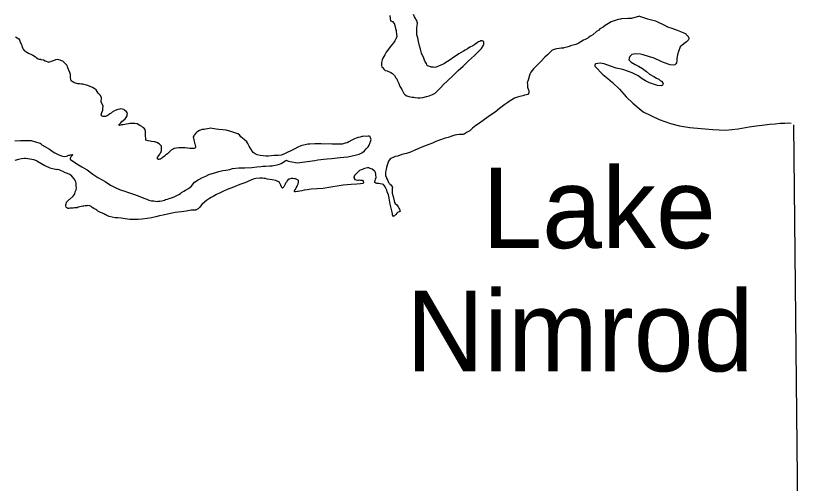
# Model space of a CAD drawing. Extents: x -83719 to 153526, y -11835 to 11446.
# Drawn here: x -2511.6 to -2340.9, y -912 to -809.8 of the extents above; entities that cross this region are included whole.
import ezdxf

# ---------------------------------------------------------------- set-up
doc = ezdxf.new("R2010")
doc.units = 0
doc.layers.add('Level 2', color=7, linetype='Continuous')
doc.layers.add('Level 9', color=7, linetype='Continuous')

msp = doc.modelspace()

# ---------------------------------------------------------------- linework, layer by layer
at = {"layer": 'Level 2'}
msp.add_lwpolyline([(-2341.72, -833.65), (-2340.87, -917.74), (-2428.7, -919.72), (-2427.14, -1008.01)], dxfattribs=at)
at = {"layer": 'Level 9'}
for points in [[(-2429.85, -809.82), (-2429.76, -810.45), (-2429.72, -810.95), (-2429.68, -810.95), (-2429.51, -811.04), (-2429.28, -811.14), (-2429.24, -811.14), (-2428.97, -811.46), (-2428.86, -811.66), (-2428.78, -812.09), (-2428.71, -812.26), (-2428.64, -812.62), (-2428.49, -813.09), (-2428.45, -813.29), (-2428.37, -813.88), (-2428.35, -814.42), (-2428.48, -814.75), (-2428.79, -815.36), (-2429.05, -815.74), (-2429.44, -816.22), (-2429.79, -816.63), (-2430.18, -817.17), (-2430.63, -817.82)], [(-2415.97, -818.94), (-2416.08, -819.02), (-2416.47, -819.36), (-2417.26, -819.85), (-2417.65, -820.1), (-2417.95, -820.27), (-2418.48, -820.59), (-2419.1, -820.77), (-2419.73, -821.09), (-2420.06, -821.13), (-2420.29, -821.1), (-2420.6, -821.05), (-2420.86, -821.05), (-2420.93, -821.02), (-2421.43, -820.9), (-2421.67, -820.78), (-2421.78, -820.58), (-2421.88, -820.31), (-2422.13, -819.92), (-2422.27, -819.59), (-2422.45, -819.13), (-2422.92, -818.01), (-2423.17, -817.14), (-2423.36, -816.42), (-2423.59, -815.49), (-2423.74, -814.69), (-2423.93, -814.03), (-2423.98, -813.4), (-2423.99, -812.93), (-2423.96, -812.69), (-2423.94, -812.43), (-2423.88, -812.12), (-2423.85, -811.89), (-2423.83, -811.59), (-2423.83, -811.45), (-2423.87, -811.26), (-2423.98, -810.92), (-2424.05, -810.79), (-2424.16, -810.6), (-2424.26, -810.43), (-2424.5, -810.07), (-2424.72, -809.61)], [(-2375.36, -809.93), (-2377.1, -810.43), (-2377.47, -810.44), (-2377.87, -810.45), (-2379.3, -810.56), (-2379.5, -810.59), (-2380.03, -810.68), (-2380.43, -810.79), (-2381.12, -811.07), (-2381.52, -811.22), (-2382.11, -811.57), (-2382.47, -811.78), (-2382.86, -811.99), (-2383.25, -812.33), (-2383.71, -812.55), (-2383.98, -812.72), (-2384.2, -812.99), (-2384.73, -813.28), (-2385.51, -814.03), (-2386, -814.31), (-2386.43, -814.56), (-2386.59, -814.73), (-2387.18, -815.05), (-2387.54, -815.19), (-2388.17, -815.54), (-2388.72, -815.89), (-2389.25, -816.11), (-2389.85, -816.29), (-2390.41, -816.44), (-2390.71, -816.58), (-2391.2, -816.69), (-2391.83, -816.88), (-2391.9, -816.91), (-2392.23, -816.92), (-2392.43, -816.96), (-2392.89, -817.01), (-2393.39, -817.09), (-2393.76, -817.13), (-2394.38, -817.38), (-2394.84, -817.8), (-2395.39, -818.41), (-2396.04, -818.9), (-2396.88, -819.82), (-2397.21, -820.2), (-2397.86, -820.78), (-2398.47, -821.47), (-2399.09, -822.19), (-2399.31, -822.59), (-2399.46, -823.1), (-2399.64, -823.94), (-2399.8, -824.28), (-2399.86, -824.54), (-2399.82, -824.78), (-2399.81, -825.14), (-2399.76, -825.44), (-2399.69, -825.67), (-2399.65, -825.87), (-2399.58, -826.04), (-2399.51, -826.17), (-2399.51, -826.2), (-2399.5, -826.4), (-2399.5, -826.57), (-2399.53, -826.74), (-2399.59, -826.87), (-2399.69, -827.04), (-2400.02, -827.15), (-2400.45, -827.23), (-2400.58, -827.27), (-2400.84, -827.38), (-2401.47, -827.49), (-2401.94, -827.64), (-2402.63, -827.89), (-2403.22, -828.21), (-2403.58, -828.42), (-2403.81, -828.59), (-2404.11, -828.8), (-2404.76, -829.22), (-2405.9, -830.12), (-2406.88, -830.88), (-2407.9, -831.54), (-2409.99, -833.1), (-2410.51, -833.45), (-2411.04, -833.83), (-2411.79, -834.39), (-2412.4, -834.97), (-2412.54, -835.04), (-2412.96, -835.26), (-2413.65, -835.71), (-2413.85, -835.78), (-2414.38, -835.8), (-2414.62, -835.77), (-2415.25, -835.85), (-2415.68, -835.97), (-2416.31, -836.18), (-2417.13, -836.41), (-2417.8, -836.59), (-2418.98, -837.06), (-2419.78, -837.35), (-2420.57, -837.67), (-2421.36, -837.96), (-2421.92, -838.21)], [(-2375.36, -809.93), (-2373.56, -810.51), (-2371.85, -810.96), (-2369.87, -811.94), (-2369.24, -812.27), (-2368.3, -812.56), (-2367.1, -812.98), (-2366.39, -813.28), (-2365.66, -813.6), (-2365.25, -813.83), (-2365.12, -813.96), (-2364.65, -814.46), (-2364.54, -814.79), (-2364.67, -815.13), (-2365.04, -815.56), (-2365.67, -816), (-2366.43, -816.65), (-2366.82, -817.68), (-2367.07, -818.42), (-2367.17, -819.22), (-2367.2, -819.69), (-2367.26, -820.13), (-2367.39, -820.36), (-2367.62, -820.6), (-2367.95, -820.67), (-2368.65, -820.61), (-2370.09, -820.09), (-2370.76, -819.76), (-2372.1, -819.14), (-2373.37, -818.75), (-2374.51, -818.4), (-2375.14, -818.27), (-2376.15, -818.18), (-2377.04, -818.35), (-2377.47, -818.79), (-2377.6, -819.13), (-2377.63, -819.49), (-2377.16, -820.02), (-2376.29, -820.48), (-2375.55, -820.84), (-2374.68, -821.37), (-2373.84, -822.06), (-2373.13, -822.62), (-2372.19, -823.14), (-2371.62, -823.47), (-2371.09, -823.73), (-2370.82, -824), (-2370.55, -824.16), (-2370.21, -824.49), (-2370.18, -824.73), (-2370.31, -825.03), (-2370.61, -825.13), (-2371.44, -825.07), (-2373.15, -824.52), (-2374.05, -824.1), (-2374.76, -823.6), (-2375.66, -823.01), (-2376.97, -822.32), (-2378.98, -821.58), (-2380.45, -821.29), (-2381.69, -820.87), (-2383.03, -820.38), (-2383.96, -820.22), (-2384.46, -820.26), (-2384.86, -820.37), (-2385.03, -820.44), (-2385.09, -820.67), (-2385.09, -820.9), (-2383.37, -822.72), (-2382.26, -823.58), (-2381.22, -824.44), (-2379.74, -825.89), (-2378.22, -827.54), (-2376.77, -828.96), (-2374.52, -830.84), (-2371.03, -832.54), (-2368.59, -833.42), (-2366.58, -833.93), (-2364.38, -834.25), (-2361.88, -834.46), (-2359.34, -834.73), (-2356.54, -834.84), (-2353.81, -834.54), (-2351.38, -834.15), (-2349.88, -833.87), (-2348.55, -833.72), (-2346.92, -833.54), (-2345.72, -833.46), (-2344.65, -833.35), (-2343.62, -833.31), (-2342.75, -833.23), (-2342.19, -833.31)], [(-2511.57, -814.43), (-2511.23, -814.66), (-2510.86, -814.88), (-2510.72, -815.11), (-2510.54, -815.64), (-2510.29, -816.17), (-2510.22, -816.46), (-2510.14, -816.66), (-2510.07, -816.86), (-2509.93, -817.16), (-2509.72, -817.45), (-2509.52, -817.55), (-2509.11, -817.8), (-2508.77, -818.02), (-2508.13, -818.31), (-2507.79, -818.46), (-2507.22, -818.85), (-2506.98, -819.08), (-2506.61, -819.23), (-2506.41, -819.33), (-2506.3, -819.36), (-2506.07, -819.35), (-2506.04, -819.38)], [(-2430.63, -817.82), (-2430.98, -818.36), (-2431.36, -819.11), (-2431.51, -819.48), (-2431.66, -820.08), (-2431.65, -820.65), (-2431.57, -821.05), (-2431.43, -821.15), (-2431.09, -821.6), (-2430.85, -821.83), (-2430.41, -821.92), (-2429.67, -822.23), (-2429.3, -822.46), (-2428.85, -822.94), (-2428.54, -823.4), (-2428.33, -823.63), (-2428.15, -824.06), (-2428.04, -824.39), (-2427.9, -824.65), (-2427.68, -825.31), (-2427.47, -825.61), (-2427.2, -825.97), (-2426.81, -826.83), (-2426.67, -826.99), (-2426.5, -827.12), (-2426.16, -827.31), (-2425.69, -827.46), (-2424.95, -827.64), (-2424.61, -827.67), (-2424.35, -827.73), (-2423.74, -827.78), (-2423.21, -827.76), (-2422.68, -827.68), (-2421.85, -827.49), (-2421.29, -827.34), (-2420.56, -827.09), (-2419.97, -826.74), (-2419.22, -826.02), (-2418.77, -825.57), (-2418.06, -824.81), (-2417.34, -824.16), (-2416.04, -822.92), (-2414.94, -821.79), (-2413.83, -820.86), (-2412.7, -819.73), (-2411.36, -818.52), (-2410.62, -817.8), (-2409.84, -817.01), (-2409.45, -816.46), (-2409.33, -816.06), (-2409.34, -815.76), (-2409.34, -815.53), (-2409.51, -815.4), (-2409.72, -815.3), (-2409.95, -815.34), (-2410.18, -815.45), (-2410.51, -815.56), (-2410.71, -815.7), (-2411.29, -816.15), (-2411.75, -816.43), (-2412.38, -816.75), (-2412.87, -817.06), (-2413.4, -817.37), (-2413.79, -817.62)], [(-2413.79, -817.62), (-2414.77, -818.19), (-2415.97, -818.94)], [(-2506.04, -819.38), (-2505.51, -819.46), (-2505.1, -819.68), (-2504.3, -819.96)], [(-2490, -830.65), (-2490.46, -830.93), (-2490.69, -831.1), (-2491.01, -831.31), (-2491.37, -831.55), (-2491.6, -831.69), (-2491.77, -831.76), (-2491.97, -831.87), (-2492.27, -831.88), (-2492.5, -831.85), (-2492.67, -831.79), (-2492.74, -831.72), (-2492.84, -831.63), (-2492.88, -831.56), (-2492.85, -831.46), (-2492.72, -830.99), (-2492.54, -830.48), (-2492.51, -830.15), (-2492.43, -829.54), (-2492.85, -828.76), (-2492.82, -827.72), (-2493.1, -827.23), (-2493.54, -826.74), (-2493.96, -826.02), (-2494.44, -825.73), (-2494.75, -825.5), (-2495.25, -825.32), (-2495.82, -825.1), (-2496.06, -825), (-2496.56, -824.85), (-2496.9, -824.83), (-2497.23, -824.77), (-2497.64, -824.71), (-2498, -824.69), (-2498.71, -824.51), (-2498.88, -824.42), (-2499.22, -824.22), (-2499.42, -824.1), (-2499.49, -823.8), (-2499.57, -823.33), (-2499.59, -822.7), (-2499.74, -822.27), (-2500.02, -821.58), (-2500.21, -820.98), (-2500.28, -820.72), (-2500.66, -820.33), (-2501.27, -819.77), (-2501.51, -819.68), (-2501.81, -819.59), (-2502.15, -819.47), (-2502.38, -819.44), (-2502.35, -819.44), (-2502.85, -819.48), (-2502.98, -819.52), (-2503.38, -819.7), (-2503.57, -819.81), (-2503.84, -819.88), (-2503.91, -819.91), (-2504.17, -819.96), (-2504.3, -819.96)], [(-2472.68, -836.84), (-2472.65, -836.98), (-2472.57, -837.24), (-2472.49, -837.67), (-2472.42, -837.84), (-2472.35, -838.14), (-2472.31, -838.3), (-2472.3, -838.63), (-2472.43, -838.77), (-2472.59, -838.88), (-2472.69, -838.88), (-2473.26, -838.83), (-2473.53, -838.84), (-2474.03, -838.78), (-2474.57, -838.73), (-2475.07, -838.71), (-2475.93, -838.7), (-2476.4, -838.75), (-2476.93, -838.86), (-2477.16, -839), (-2477.59, -839.21), (-2478.11, -839.73), (-2478.4, -840.01), (-2478.73, -840.21), (-2479.09, -840.49), (-2479.31, -840.73), (-2479.54, -840.9), (-2479.61, -840.97), (-2479.77, -841.04), (-2479.87, -841.15), (-2480.07, -841.19), (-2480.3, -841.26), (-2480.37, -841.26), (-2480.4, -841.23), (-2480.47, -841.2), (-2480.54, -841.17), (-2480.57, -841.13), (-2480.61, -841), (-2480.55, -840.77), (-2480.45, -840.56), (-2480.1, -840.05), (-2479.97, -839.88), (-2479.88, -839.71), (-2479.72, -839.27), (-2479.7, -838.91), (-2479.68, -838.47), (-2479.71, -838.37), (-2479.88, -838.21), (-2480.13, -837.92), (-2480.36, -837.76), (-2480.74, -837.57), (-2481.14, -837.41), (-2481.34, -837.38), (-2481.91, -837.3), (-2482.18, -837.24), (-2482.61, -837.18), (-2483.12, -837.06), (-2483.12, -837.03), (-2483.12, -836.93), (-2483.12, -836.83), (-2483.16, -836.57), (-2483.18, -836.16), (-2483.22, -835.87), (-2483.23, -835.4), (-2483.23, -835.23), (-2483.28, -834.73), (-2483.56, -834.34), (-2483.83, -834.18), (-2484.03, -834.05), (-2484.41, -833.83), (-2485.05, -833.48), (-2485.52, -833.39), (-2485.92, -833.4), (-2486.59, -833.39), (-2486.95, -833.47), (-2487.45, -833.55), (-2487.75, -833.59), (-2488.18, -833.67), (-2488.41, -833.67), (-2488.58, -833.78), (-2488.88, -833.79), (-2488.98, -833.79), (-2488.92, -833.55), (-2488.89, -833.52), (-2488.59, -833.24), (-2488.37, -832.97), (-2488.07, -832.73), (-2487.62, -832.35), (-2487.39, -832.08), (-2487.23, -831.74), (-2487.18, -831.44), (-2487.15, -831.1), (-2487.36, -830.84), (-2487.77, -830.45), (-2487.94, -830.32), (-2488.28, -830.23), (-2488.61, -830.21), (-2488.84, -830.25), (-2489.27, -830.33), (-2489.83, -830.57), (-2490, -830.65)], [(-2450.1, -841.96), (-2446.21, -841.48), (-2445.58, -841.33), (-2444.95, -841.25), (-2444.28, -841.2), (-2443.52, -841.14), (-2442.59, -841.05), (-2440.69, -840.83), (-2439.89, -840.77), (-2439.03, -840.68), (-2438.07, -840.46), (-2437.14, -840.26), (-2436.58, -840.08), (-2435.82, -839.69), (-2435.4, -839.35), (-2435.01, -838.94), (-2434.62, -838.49), (-2434.39, -838.15), (-2434.18, -837.55), (-2434.15, -837.44), (-2434.08, -837.34), (-2433.99, -837.11), (-2433.9, -836.87), (-2434, -836.67), (-2434.04, -836.57), (-2434.18, -836.21), (-2434.38, -836.18), (-2434.55, -836.19), (-2435.05, -836.2), (-2435.28, -836.17), (-2435.75, -836.22), (-2435.98, -836.26), (-2436.31, -836.4), (-2436.74, -836.48), (-2437.24, -836.6), (-2437.6, -836.74), (-2438.16, -837.05), (-2438.78, -837.41), (-2439.15, -837.58), (-2439.61, -837.66), (-2440.27, -837.88), (-2440.54, -837.92), (-2440.84, -837.93), (-2441.64, -837.92), (-2442.41, -837.87), (-2443.07, -837.86), (-2444.07, -837.89), (-2444.88, -837.84), (-2445.58, -837.83), (-2446.24, -837.85), (-2447.31, -837.88), (-2447.77, -837.92), (-2449.3, -838.23), (-2449.96, -838.58), (-2450.61, -838.94), (-2451.47, -839.33), (-2452.29, -839.72), (-2453.02, -840.07), (-2453.61, -840.29), (-2454.21, -840.37), (-2454.71, -840.35), (-2455.14, -840.4), (-2455.77, -840.48), (-2456.37, -840.53), (-2456.91, -840.51), (-2457.51, -840.46), (-2458.18, -840.35), (-2458.82, -840.23), (-2459.29, -840.01), (-2459.66, -839.75), (-2459.84, -839.49), (-2460.19, -838.93), (-2460.57, -838.31), (-2460.89, -837.72), (-2461.1, -837.42), (-2461.64, -836.9), (-2462.36, -836.32), (-2462.71, -835.87), (-2463.05, -835.67), (-2463.89, -835.33), (-2464.76, -835.05), (-2465.6, -834.81), (-2466.34, -834.76), (-2467.17, -834.72), (-2467.74, -834.6), (-2468.62, -834.46), (-2468.95, -834.44), (-2469.68, -834.56), (-2470.08, -834.6), (-2470.41, -834.68), (-2470.81, -834.72), (-2471.4, -834.94), (-2471.77, -835.11), (-2471.96, -835.29), (-2472.19, -835.53), (-2472.58, -835.9), (-2472.58, -835.94), (-2472.67, -836.07), (-2472.77, -836.31), (-2472.72, -836.68), (-2472.68, -836.84)], [(-2505.81, -838.03), (-2505.84, -838.04), (-2506.01, -837.91), (-2506.18, -837.78), (-2507.13, -837.44), (-2508.13, -837.17), (-2509.43, -837.2), (-2510.49, -837.2), (-2511.76, -837.27)], [(-2505.84, -838.04), (-2504.17, -838.98), (-2503.6, -839.4), (-2503.33, -839.56), (-2502.98, -839.82), (-2502.54, -840.04), (-2502.14, -840.23), (-2501.57, -840.48), (-2501.23, -840.54), (-2500.93, -840.63), (-2500.43, -840.55), (-2500.27, -840.44), (-2499.94, -840.33), (-2499.74, -840.3), (-2499.57, -840.22), (-2499.27, -840.22), (-2499.14, -840.18), (-2499.1, -840.24), (-2499.14, -840.28), (-2499.17, -840.31), (-2499.36, -840.49), (-2499.36, -840.52), (-2499.43, -840.59), (-2499.52, -840.76), (-2499.55, -840.82), (-2499.65, -841.03), (-2499.68, -841.2), (-2499.58, -841.26), (-2498.22, -842.19), (-2497.84, -842.41), (-2497.1, -842.86), (-2495.95, -843.5), (-2494.68, -844.46), (-2493.63, -845.2), (-2492.04, -846.09), (-2490.82, -846.83), (-2490, -847.3), (-2488.89, -847.77), (-2488.45, -847.96), (-2487.74, -848.18), (-2487.37, -848.3), (-2485.83, -848.79), (-2484.81, -849.2), (-2483.94, -849.54), (-2483.33, -849.76), (-2482.93, -849.91), (-2482.49, -850.1), (-2481.92, -850.25), (-2481.38, -850.3), (-2480.64, -850.42), (-2480.45, -850.34), (-2480.11, -850.37), (-2479.61, -850.29), (-2479.02, -850.1), (-2478.82, -850), (-2478.39, -849.89), (-2478.06, -849.74), (-2477.33, -849.52), (-2476.77, -849.31), (-2476.51, -849.17), (-2475.92, -848.92), (-2475.59, -848.64), (-2475.36, -848.47), (-2474.84, -848.19), (-2474.44, -847.97), (-2473.82, -847.56), (-2473.46, -847.28), (-2473.26, -847.17), (-2472.52, -846.19), (-2471.71, -845.66), (-2470.79, -845.17), (-2470.06, -844.88), (-2469.4, -844.53), (-2467.61, -844.05), (-2467.22, -843.9), (-2466.32, -843.68), (-2465.69, -843.59), (-2464.8, -843.4), (-2464.2, -843.22), (-2462.84, -843.08), (-2461.51, -843.04), (-2460.01, -842.97), (-2458.88, -842.84), (-2458.05, -842.75), (-2457.58, -842.67), (-2456.98, -842.72), (-2456.08, -842.66), (-2455.51, -842.64), (-2455.22, -842.57), (-2454.45, -842.45), (-2453.92, -842.3), (-2453.56, -842.12), (-2453.23, -841.91), (-2452.71, -841.56), (-2452.45, -841.42), (-2452.35, -841.45), (-2452.21, -841.52), (-2451.98, -841.58), (-2451.24, -841.79), (-2450.46, -841.94), (-2450.1, -841.96)], [(-2421.92, -838.21), (-2422.88, -838.57), (-2423.5, -838.85), (-2424.39, -839.21), (-2425.32, -839.64), (-2426.21, -839.93), (-2427.2, -840.19), (-2428.09, -840.51), (-2428.69, -840.63), (-2429.78, -841.13), (-2430.16, -841.64), (-2430.28, -842.08), (-2430.44, -842.48), (-2430.56, -842.99), (-2430.74, -843.73), (-2430.8, -844.03), (-2430.82, -844.43), (-2430.78, -844.73), (-2430.56, -845.26), (-2430.52, -845.49), (-2430.28, -845.85), (-2430.17, -846.25), (-2430.03, -846.41), (-2429.96, -846.51), (-2429.86, -846.64), (-2429.62, -846.8), (-2429.37, -847.16), (-2429.3, -847.39), (-2429.33, -847.59), (-2429.36, -847.83), (-2429.33, -848.59), (-2429.15, -849.36), (-2428.92, -850.25), (-2428.81, -850.62), (-2428.67, -850.88), (-2428.36, -851.14), (-2428.05, -851.6), (-2427.88, -851.86), (-2427.74, -852.09), (-2427.66, -852.29), (-2427.59, -852.59), (-2427.76, -852.62), (-2427.82, -852.66), (-2428.05, -852.76), (-2428.18, -852.84), (-2428.35, -852.97), (-2428.54, -853.25), (-2428.7, -853.38), (-2428.83, -853.55), (-2428.99, -853.66), (-2429.06, -853.69), (-2429.24, -853.37), (-2429.24, -853.1), (-2429.32, -852.73), (-2429.39, -852.47), (-2429.54, -851.87), (-2429.77, -851.04), (-2430.01, -849.68), (-2430.16, -848.98), (-2430.41, -848.32), (-2430.52, -847.93), (-2430.7, -847.53), (-2431.01, -847.01), (-2431.26, -846.68), (-2431.52, -846.62), (-2431.99, -846.53), (-2432.23, -846.5), (-2432.46, -846.51), (-2432.66, -846.48), (-2432.93, -846.42), (-2433.14, -846.26), (-2433.14, -846.23), (-2433.1, -846.23), (-2433.08, -845.83), (-2432.99, -845.52), (-2432.86, -845.19), (-2432.88, -844.62), (-2432.89, -844.42), (-2432.96, -844.09), (-2433.14, -843.83), (-2433.24, -843.73), (-2433.68, -843.34), (-2434.12, -843.19), (-2434.46, -843.06), (-2434.73, -843.04), (-2435.39, -843.25), (-2435.68, -843.33), (-2436.11, -843.54), (-2436.48, -843.68), (-2436.87, -844), (-2437.09, -844.24), (-2437.35, -844.51), (-2437.58, -844.75), (-2437.67, -844.95), (-2437.7, -845.09), (-2437.71, -845.02), (-2437.67, -845.22), (-2437.63, -845.42), (-2437.52, -845.62), (-2437.22, -845.71), (-2436.92, -845.77)], [(-2506.92, -841.57), (-2507.61, -841.32), (-2509.35, -841.04), (-2509.62, -841.01), (-2510.28, -841.13), (-2510.91, -841.22), (-2511.77, -841.44)], [(-2506.92, -841.57), (-2505.16, -842.59), (-2504.08, -843.1), (-2502.59, -843.45)], [(-2476.04, -852.73), (-2476.74, -852.81), (-2477.4, -853), (-2478.4, -853.19), (-2479.36, -853.42), (-2480.16, -853.57), (-2480.92, -853.76), (-2481.88, -853.99), (-2482.81, -854.15), (-2483.94, -854.28), (-2484.84, -854.34), (-2485.6, -854.36), (-2486.3, -854.38), (-2486.61, -854.32), (-2487.61, -854.18), (-2488.51, -854.07), (-2489.28, -853.99), (-2489.82, -853.97), (-2490.49, -853.83), (-2491.16, -853.68), (-2491.63, -853.46), (-2491.87, -853.36), (-2492.07, -853.27), (-2492.27, -853.14), (-2492.58, -852.95), (-2493.02, -852.79), (-2493.59, -852.51), (-2493.8, -852.35), (-2494.07, -852.16), (-2494.34, -852.03), (-2494.48, -851.97), (-2494.82, -851.71), (-2495.09, -851.48), (-2495.19, -851.45), (-2495.43, -851.36), (-2495.76, -851.33), (-2496.03, -851.34), (-2496.36, -851.38), (-2496.69, -851.43), (-2496.92, -851.43), (-2497.22, -851.51), (-2497.26, -851.54), (-2497.55, -851.58), (-2497.89, -851.66), (-2498.15, -851.77), (-2498.22, -851.77), (-2498.68, -851.78), (-2499.01, -851.86), (-2499.45, -851.9), (-2499.58, -851.91), (-2499.71, -851.91), (-2499.95, -851.95), (-2500.15, -851.92), (-2500.28, -851.83), (-2500.45, -851.7), (-2500.55, -851.63), (-2500.63, -851.4), (-2500.66, -851.4), (-2500.63, -851.27), (-2500.57, -851.13), (-2500.57, -851.07), (-2500.54, -850.97), (-2500.45, -850.6), (-2500.39, -850.53), (-2500.19, -850.26), (-2500.06, -850.19), (-2499.87, -850.01), (-2499.7, -849.94), (-2498.99, -849.29), (-2498.79, -848.95), (-2498.67, -848.74), (-2498.55, -848.34), (-2498.42, -848.04), (-2498.36, -847.84), (-2498.3, -847.47), (-2498.31, -847.03), (-2498.36, -846.43), (-2498.41, -846.1), (-2498.51, -845.97), (-2498.76, -845.48), (-2499.27, -844.92), (-2499.75, -844.54), (-2500.23, -844.28), (-2500.9, -844.07), (-2501.04, -843.94), (-2501.78, -843.62), (-2502.08, -843.5), (-2502.42, -843.47), (-2502.59, -843.45)], [(-2436.92, -845.77), (-2436.68, -845.76), (-2436.45, -845.72), (-2436.28, -845.75), (-2436.05, -845.74), (-2435.95, -845.77), (-2435.82, -845.8), (-2435.71, -846), (-2435.64, -846.07), (-2435.6, -846.2), (-2435.63, -846.37), (-2435.73, -846.47), (-2436.26, -846.58), (-2437.06, -846.64), (-2438.29, -846.74), (-2440.05, -846.89), (-2440.95, -846.98), (-2442.71, -847.26), (-2444.4, -847.58), (-2447, -847.71), (-2447.93, -847.87), (-2448.56, -847.96), (-2449.06, -848.07), (-2449.52, -848.19), (-2449.85, -848.26), (-2449.99, -848.26), (-2450.45, -848.31), (-2450.52, -848.28), (-2450.55, -848.28), (-2450.59, -848.28), (-2450.66, -848.22), (-2450.69, -848.08), (-2450.69, -848.05), (-2450.6, -847.91), (-2450.47, -847.78), (-2450.41, -847.58), (-2450.28, -847.41), (-2450.12, -847.1), (-2449.99, -846.86), (-2449.87, -846.56), (-2449.78, -846.22), (-2449.79, -845.86), (-2449.89, -845.79), (-2450.13, -845.63), (-2450.47, -845.47), (-2450.7, -845.45), (-2451, -845.42), (-2451.43, -845.43), (-2451.73, -845.51), (-2451.96, -845.58), (-2452.09, -845.69), (-2452.29, -845.93), (-2452.45, -846.2), (-2452.61, -846.4), (-2452.7, -846.64), (-2452.86, -846.94), (-2452.99, -847.21), (-2453.28, -847.49), (-2453.38, -847.49), (-2453.52, -847.23), (-2453.63, -846.86), (-2453.91, -846.24), (-2454.15, -846.11), (-2454.73, -845.83), (-2455.53, -845.71), (-2456.03, -845.59), (-2456.64, -845.51), (-2456.97, -845.42), (-2457.27, -845.4), (-2457.64, -845.34), (-2458.24, -845.32), (-2459.11, -845.41), (-2459.67, -845.56), (-2461.55, -846.38), (-2462.57, -846.74), (-2463.96, -847.28), (-2465.38, -847.82), (-2466.3, -848.25), (-2467.02, -848.57), (-2467.68, -848.89), (-2468.43, -849.34), (-2468.83, -849.55), (-2469.22, -849.8), (-2469.88, -850.22), (-2470.3, -850.56), (-2470.89, -851.08), (-2471.18, -851.42), (-2471.34, -851.63), (-2471.44, -851.73), (-2471.63, -851.94), (-2471.7, -852), (-2471.89, -852.11), (-2472.06, -852.21), (-2472.22, -852.25), (-2472.32, -852.29), (-2472.49, -852.29), (-2472.92, -852.3), (-2473.25, -852.31), (-2474.35, -852.51), (-2475.31, -852.67), (-2476.04, -852.73)]]:
    msp.add_lwpolyline(points, dxfattribs=at)

# ---------------------------------------------------------------- texts
for s, p in [('Lake', (-2409.68, -860.61)), ('Nimrod', (-2426.28, -887.52))]:
    msp.add_text(s, height=17.6, dxfattribs=at).set_placement(p)

doc.saveas('drawing.dxf')
